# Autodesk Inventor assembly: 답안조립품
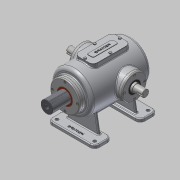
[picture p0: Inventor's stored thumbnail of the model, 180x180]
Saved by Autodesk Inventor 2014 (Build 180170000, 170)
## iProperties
Created: 2016-06
Part Number: 답안조립품
Document SubType Name: Assembly
Designer: user
Mass: 8166.81 g
Surface Area: 4241.81 cm^2
Volume: 1852.23 cm^3
Density: 4.40919 g/cm^3
Author: user
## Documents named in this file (15)
- C:\Users\user\Desktop\Manufacturing1급-김민한\답안조립품.iam
- C:\Users\user\Desktop\Manufacturing1급-김민한\본체.ipt
- C:\Users\user\Desktop\Manufacturing1급-김민한\상부커버.ipt
- C:\Users\user\Desktop\Manufacturing1급-김민한\육각머리볼트 M4.ipt
- C:\Users\user\Desktop\Manufacturing1급-김민한\베어링 6205.ipt
- 베어링 6205.ipt
- C:\Users\user\Desktop\Manufacturing1급-김민한\축 커버.ipt
- C:\Users\user\Desktop\Manufacturing1급-김민한\오일실.ipt
- 오일실.ipt
- C:\Users\user\Desktop\Manufacturing1급-김민한\볼트 M4x0.7.ipt
- C:\Users\user\Desktop\Manufacturing1급-김민한\슬라이드 커버.ipt
- C:\Users\user\Desktop\Manufacturing1급-김민한\편심축.ipt
- C:\Users\user\Desktop\Manufacturing1급-김민한\부시.ipt
- C:\Users\user\Desktop\Manufacturing1급-김민한\가변스프링.ipt
- C:\Users\user\Desktop\Manufacturing1급-김민한\슬라이드.ipt
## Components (13 placed, 2 different names)
1. 가변스프링:1
2. M4x0.7:1
3. M4x0.7:2
4. M4x0.7:3
5. M4x0.7:4
6. M4x0.7:5
7. M4x0.7:6
8. M4x0.7:7
9. M4x0.7:8
10. M4x0.7:9
11. M4x0.7:10
12. M4x0.7:11
13. M4x0.7:12
